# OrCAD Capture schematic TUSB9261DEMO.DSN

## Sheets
1 PAGE1: size C; title: TUSB9261 DEMO EVM; rev: A; company: Texas Instruments; note: TUSB9261 DEMO
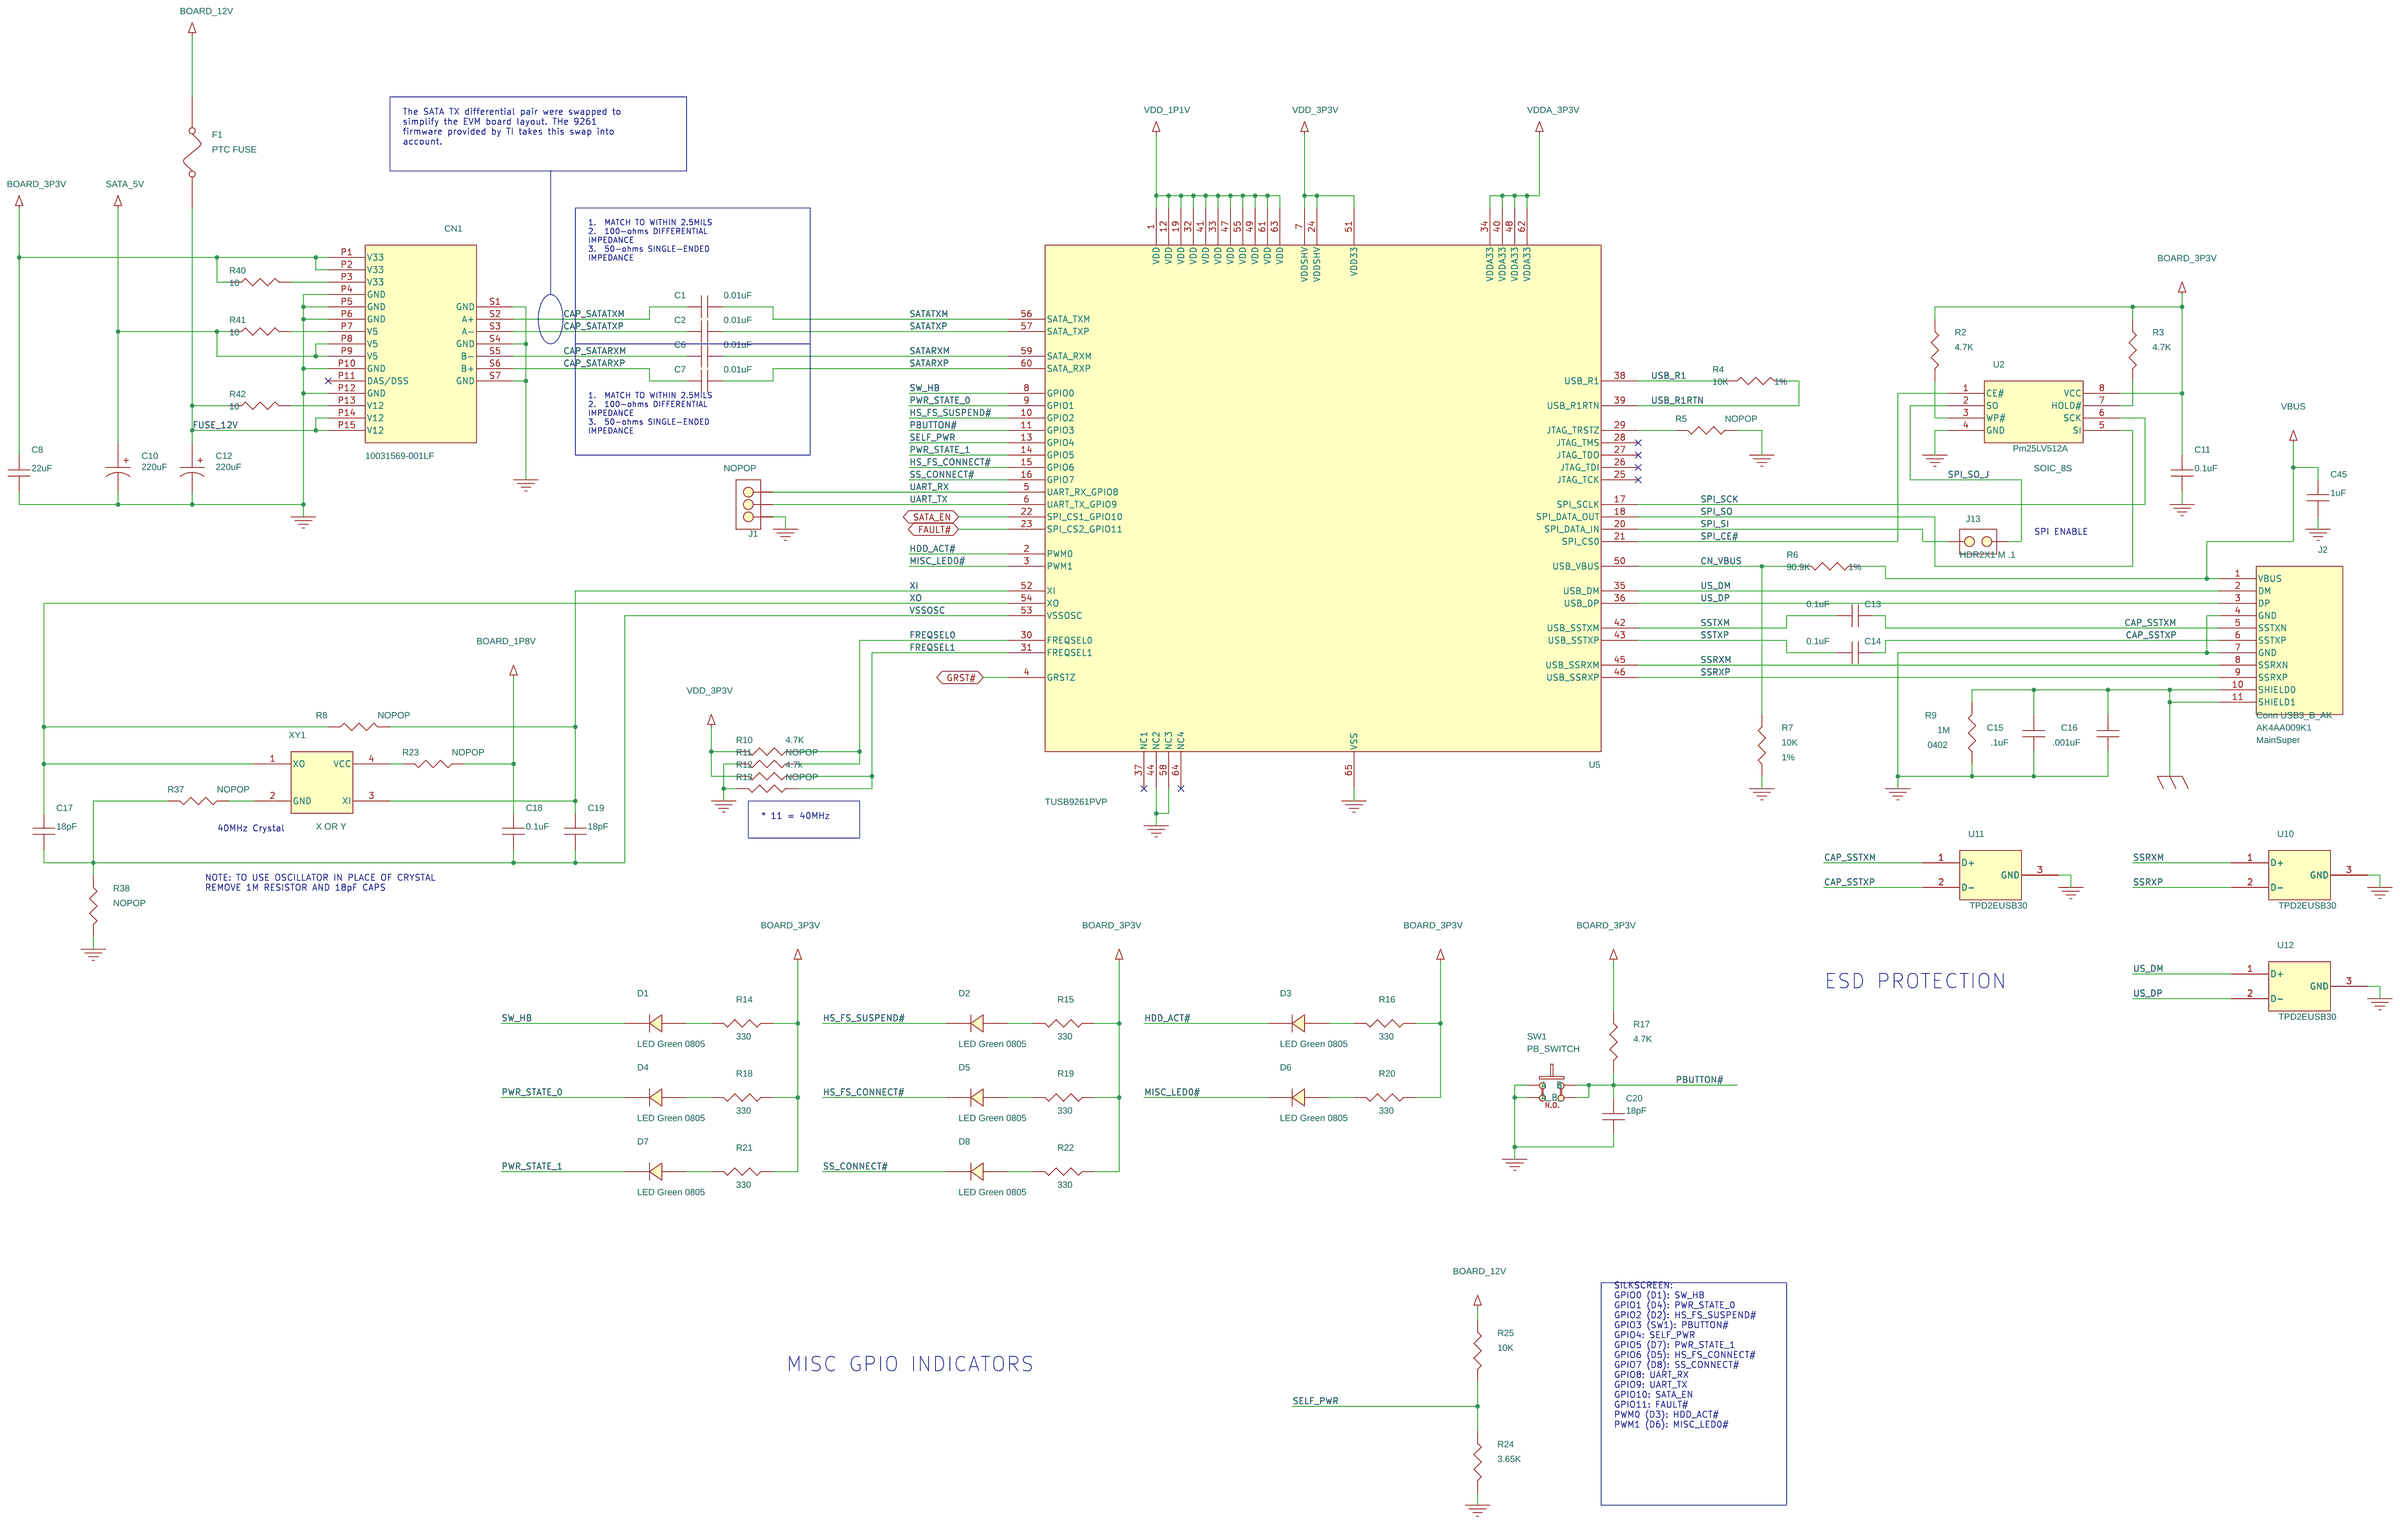
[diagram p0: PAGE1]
2 PAGE2: size C; note: POWER
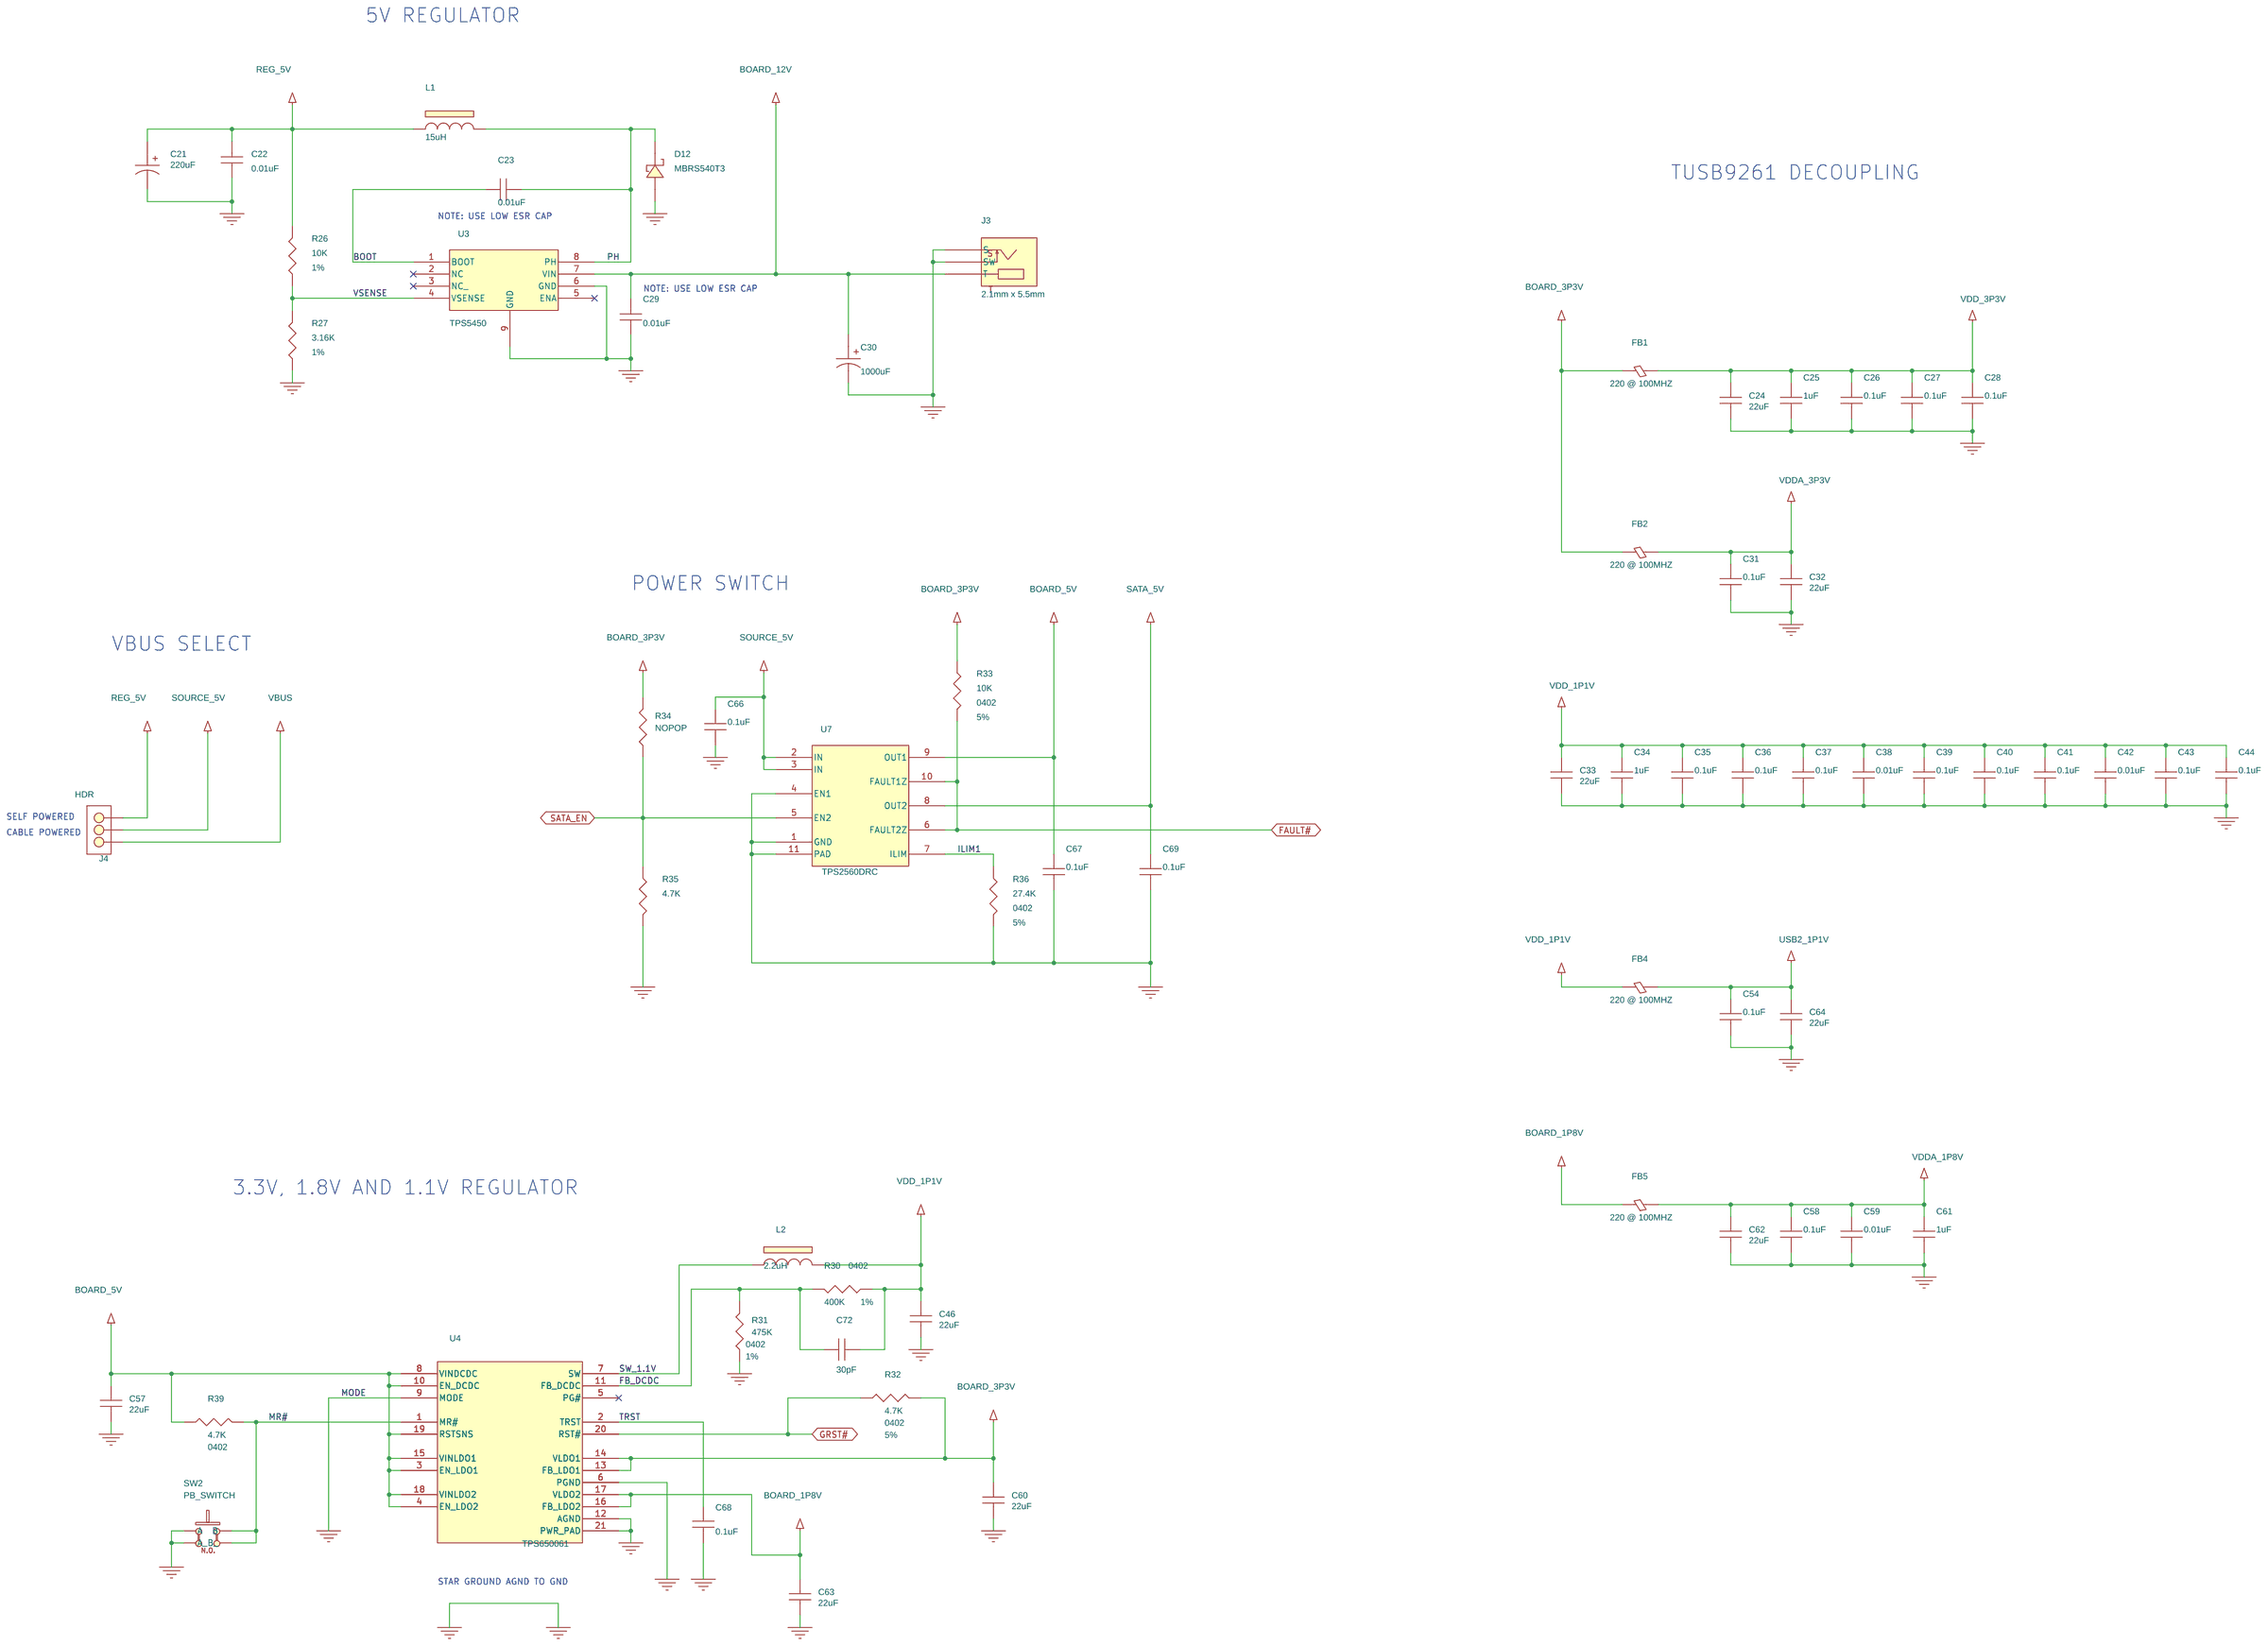
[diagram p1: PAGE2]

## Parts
sheet PAGE1
C1  0.01uF  [0402]
C2  0.01uF  [0402]
C6  0.01uF  [0402]
C7  0.01uF  [0402]
C8  22uF  [0805]
C10  220uF  [THCAP_2P5MM]
C11  0.1uF  [0402]
C12  220uF  [THCAP_2P5MM]
C13  0.1uF  [0201]
C14  0.1uF  [0201]
C15  .1uF  [0402]
C16  .001uF  [0402]
C17  18pF  [0402]
C18  0.1uF  [0402]
C19  18pF  [0402]
C20  18pF  [0402]
C45  1uF  [0402]
CN1  10031569-001LF  [CONN_10031569]
D1  LED Green 0805  [0805]
D2  LED Green 0805  [0805]
D3  LED Green 0805  [0805]
D4  LED Green 0805  [0805]
D5  LED Green 0805  [0805]
D6  LED Green 0805  [0805]
D7  LED Green 0805  [0805]
D8  LED Green 0805  [0805]
F1  PTC FUSE  [FUSE_2920L]
J1  NOPOP  [eprt-head-00001-0000]
J2  Conn USB3_B_AK  [USB3_TYPEB_AK4AA009]
J13  HDR2X1 M .1  [HDR_2X1]
R2  4.7K  [0402]
R3  4.7K  [0402]
R4  10K  [0402]
R5  NOPOP  [0402]
R6  90.9K  [0402]
R7  10K  [0402]
R8  NOPOP  [0402]
R9  1M  [0402]
R10  4.7K  [0402]
R11  NOPOP  [0402]
R12  4.7k  [0402]
R13  NOPOP  [0402]
R14  330  [0402]
R15  330  [0402]
R16  330  [0402]
R17  4.7K  [0402]
R18  330  [0402]
R19  330  [0402]
R20  330  [0402]
R21  330  [0402]
R22  330  [0402]
R23  NOPOP  [0402]
R24  3.65K  [0402]
R25  10K  [0402]
R37  NOPOP  [0402]
R38  NOPOP  [0402]
R40  10  [0805]
R41  10  [0805]
R42  10  [0805]
SW1  PB_SWITCH  [SW_MOM_2NO]
U2  Pm25LV512A  [SOIC_8S]
U5  TUSB9261PVP  [ironwood_64pin_c9508]
U10  TPD2EUSB30  [DRT_r_pdso_n3_sot23]
U11  TPD2EUSB30  [DRT_r_pdso_n3_sot23]
U12  TPD2EUSB30  [DRT_r_pdso_n3_sot23]
XY1  X OR Y  [ECX-53B]
sheet PAGE2
C21  220uF  [THCAP_2P5MM]
C22  0.01uF  [0402]
C23  0.01uF  [0402]
C24  22uF  [0805]
C25  1uF  [0402]
C26  0.1uF  [0402]
C27  0.1uF  [0402]
C28  0.1uF  [0402]
C29  0.01uF  [0402]
C30  1000uF  [THCAP_5MM]
C31  0.1uF  [0402]
C32  22uF  [0805]
C33  22uF  [0805]
C34  1uF  [0402]
C35  0.1uF  [0402]
C36  0.1uF  [0402]
C37  0.1uF  [0402]
C38  0.01uF  [0402]
C39  0.1uF  [0402]
C40  0.1uF  [0402]
C41  0.1uF  [0402]
C42  0.01uF  [0402]
C43  0.1uF  [0402]
C44  0.1uF  [0402]
C46  22uF  [0805]
C54  0.1uF  [0402]
C57  22uF  [0805]
C58  0.1uF  [0402]
C59  0.01uF  [0402]
C60  22uF  [0805]
C61  1uF  [0402]
C62  22uF  [0805]
C63  22uF  [0805]
C64  22uF  [0805]
C66  0.1uF  [0402]
C67  0.1uF  [0402]
C68  0.1uF  [0402]
C69  0.1uF  [0402]
C72  30pF  [0402]
D12  MBRS540T3  [DIODE_SMC]
FB1  220 @ 100MHZ  [0603]
FB2  220 @ 100MHZ  [0603]
FB4  220 @ 100MHZ  [0603]
FB5  220 @ 100MHZ  [0603]
J3  2.1mm x 5.5mm  [PJ-202AH]
J4  HDR  [eprt-head-00001-0000]
L1  15uH  [DR127]
L2  2.2uH  [IND_SM_VLCF_4X4X2MM]
R26  10K  [0402]
R27  3.16K  [0402]
R30  400K  [0402]
R31  475K  [0402]
R32  4.7K  [0402]
R33  10K  [0402]
R34  NOPOP  [0402]
R35  4.7K  [0402]
R36  27.4K  [0402]
R39  4.7K  [0402]
SW2  PB_SWITCH  [SW_MOM_2NO]
U3  TPS5450  [DDA_R-PDSO-G8]
U4  TPS650061  [RUK_s-pqfp-n20]
U7  TPS2560DRC  [DRC_S_PVSON_N10]

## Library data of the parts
C1 C2 C6-C8 C11 C13-C20 C22-C29 C31-C46 C54 C57-C64 C66-C69 C72 = CAP_NP
C10 C12 C21 = CAP_POL: Manuf: Panasonic; Manuf PN: ECA-1CM221
CN1 = 0876781001: Manuf: FCI
D1-D8 = DIODE: Manuf: Lumex; Manuf PN: SML-LX0805GC-TR; TI_Silktext: LEDG1
F1 = FUSE: Manuf: Littelfuse; Manuf PN: 2920L200/24DR
J1 J4 = HDR3X1_M_.1
J2 = USB3_TYPEB_CONNECTOR: Connector USB3 TYPE B; Manuf: MainSuper; Manuf PN: AK4AA009K1; Manufacturer: MainSuper; Manufacturer's Part#: AK4AA009K1; PART_NUMBER: USB3_UP0; Part#: eprt-conn-00064-0100; Status: OK; TI_Silktext: USB3_UP0
J13 = HDR2X1_M_.1
R2 R3 R5 R8-R25 R32-R42 = R: Tolerance: 5%
R4 R6 R7 R26 R27 R30 R31 = R: Tolerance: 1%
SW1 SW2 = PB_SWITCH_0: Manuf: OMRON; Manuf PN: B3SN-3012P; PART_NUMBER: BRD_RESETN; Part#: B3SN-3012P; TI_Silktext: BRD_RESETN
U2 = Pm25LV512A: Manuf: Chingistek; Manuf PN: Pm25LV512A-100SCE
U5 = TUSB9260PAP_0
U10-U12 = TPD2E009: Manuf PN: TPD2EUSB30DRT
XY1 = X_OR_Y: Manuf PN: ECS-250-20-30B-TR
C30 = CAP_POL: Manuf: Panasonic; Manuf PN: ECA-1CM102
D12 = DIODE_SCHOTTKY: Manuf: On Semiconductor; Manuf PN: MBRS540T3G
FB1 FB2 FB4 FB5 = FERRITE_BEAD: FBEAD 1000@100MHz; Device: BEAD1806; MFC: MuRata; Manuf: MuRata; Manuf PN: BLM18EG221SN1D; Part Number: BLM18EG221SN1D; Part#: BLM18EG221SN1D
J3 = BNC_2: POWER JACK; COST: .12; MANUF: CUI STACK; PART_NUMBER: 5V_SUPPLY; TI_Silktext: 5V_SUPPLY
L1 = INDUCTOR_FERRITE: Manuf: Coiltronics; Manuf PN: DR127-150-R
L2 = INDUCTOR_FERRITE: Manuf: TDK; Manuf PN: VLCF4020T-2R2N1R7
U3 = TPS5450_2: Manuf: Texas Instruments; Manuf PN: TPS5450DDAR
U4 = TPS650061_0
U7 = TPS2560DRC_1: Manuf: Texas Instruments

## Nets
AGND: C8.2 C10.2 C11.2 C12.2 C15.1 C16.1 C20.1 C21.2 C22.1 C24.2 C25.2 C26.2 C27.2 C28.2 C29.1 C30.2 C31.2 C32.2 C33.2 C34.2 C35.2 C36.2 C37.2 C38.2 C39.2 C40.2 C41.2 C42.2 C43.2 C44.2 C45.2 C46.2 C54.2 C57.2 C58.2 C59.2 C60.2 C61.2 C62.2 C63.2 C64.2 C66.2 C67.2 C68.2 C69.2 CN1.P4(GND) CN1.P5(GND) CN1.P6(GND) CN1.P10(GND) CN1.P12(GND) CN1.S1(GND) CN1.S4(GND) CN1.S7(GND) D12.1(ANODE) J1.1 J2.4(GND) J2.7(GND) J3.2(S) J3.3(SW) R5.1 R7.1 R9.2 R11.2 R13.2 R24.2 R27.1 R31.1 R35.2 R36.2 R38.2 SW1.1(A) SW1.2(A_) SW2.1(A) SW2.2(A_) U2.4(GND) U3.6(GND) U3.9(GND) U4.6(PGND) U4.9(MODE) U4.12(AGND) U4.21(PWR_PAD) U5.44(NC2) U5.58(NC3) U5.65(VSS) U7.1(GND) U7.4(EN1) U7.11(PAD) U10.3(GND) U11.3(GND) U12.3(GND)
GND_EARTH: C15.2 C16.2 J2.10(SHIELD0) J2.11(SHIELD1) R9.1
VBUS: C45.1 J2.1(VBUS) J4.1 R6.1
VDD_1P1V: C33.1 C34.1 C35.1 C36.1 C37.1 C38.1 C39.1 C40.1 C41.1 C42.1 C43.1 C44.1 C46.1 C72.2 FB4.1 L2.2 R30.1 U5.1(VDD) U5.12(VDD) U5.19(VDD) U5.32(VDD) U5.33(VDD) U5.41(VDD) U5.47(VDD) U5.49(VDD) U5.55(VDD) U5.61(VDD) U5.63(VDD)
VDD_3P3V: C24.1 C25.1 C26.1 C27.1 C28.1 FB1.2 R10.2 R12.2 U5.7(VDDSHV) U5.24(VDDSHV) U5.51(VDD33)
VDDA_1P8V: C58.1 C59.1 C61.1 C62.1 FB5.2
VDDA_3P3V: C31.1 C32.1 FB2.2 U5.34(VDDA33) U5.40(VDDA33) U5.48(VDDA33) U5.62(VDDA33)
VSSOSC: C17.2 C18.2 C19.2 R37.2 R38.1 U5.53(VSSOSC)
BOARD_1P8V: C18.1 C63.1 FB5.1 R23.1 U4.16(FB_LDO2) U4.17(VLDO2)
BOARD_3P3V: C8.1 C11.1 C60.1 CN1.P1(V33) CN1.P2(V33) FB1.1 FB2.1 R2.1 R3.1 R14.1 R15.1 R16.1 R17.1 R18.1 R19.1 R20.1 R21.1 R22.1 R32.2 R33.1 R34.2 R40.1 U2.8(VCC) U4.13(FB_LDO1) U4.14(VLDO1)
BOARD_5V: C57.1 C67.1 R39.1 U4.3(EN_LDO1) U4.4(EN_LDO2) U4.8(VINDCDC) U4.10(EN_DCDC) U4.15(VINLDO1) U4.18(VINLDO2) U4.19(RSTSNS) U7.9(OUT1)
BOARD_12V: C29.2 C30.1 F1.2 J3.1(T) R25.1 U3.7(VIN)
BOOT: C23.1 U3.1(BOOT)
CAP_SATARXM: C6.1 CN1.S5(B-)
CAP_SATARXP: C7.1 CN1.S6(B+)
CAP_SATATXM: C1.1 CN1.S2(A+)
CAP_SATATXP: C2.1 CN1.S3(A-)
CAP_SSTXM: C13.1 J2.5(SSTXN) U11.1(D+)
CAP_SSTXP: C14.1 J2.6(SSTXP) U11.2(D-)
CN_VBUS: R6.2 R7.2 U5.50(USB_VBUS)
FAULT#: R33.2 U5.23(SPI_CS2_GPIO11) U7.6(FAULT2Z) U7.10(FAULT1Z)
FB_DCDC: C72.1 R30.2 R31.2 U4.11(FB_DCDC)
FREQSEL0: R10.1 R11.1 U5.30(FREQSEL0)
FREQSEL1: R12.1 R13.1 U5.31(FREQSEL1)
FUSE_12V: C12.1 CN1.P14(V12) CN1.P15(V12) F1.1 R42.1
GRST#: R32.1 U4.20(RST#) U5.4(GRSTZ)
HDD_ACT#: D3.2(K) U5.2(PWM0)
HS_FS_CONNECT#: D5.2(K) U5.15(GPIO6)
HS_FS_SUSPEND#: D2.2(K) U5.10(GPIO2)
ILIM1: R36.1 U7.7(ILIM)
MISC_LED0#: D6.2(K) U5.3(PWM1)
MR#: R39.2 SW2.3(B_) SW2.4(B) U4.1(MR#)
PBUTTON#: C20.2 R17.2 SW1.3(B_) SW1.4(B) U5.11(GPIO3)
PH: C23.2 D12.2(CATHODE) L1.2 U3.8(PH)
PWR_STATE_0: D4.2(K) U5.9(GPIO1)
PWR_STATE_1: D7.2(K) U5.14(GPIO5)
REG_5V: C21.1 C22.2 J4.3 L1.1 R26.2
SATA_5V: C10.1 C69.1 CN1.P8(V5) CN1.P9(V5) R41.1 U7.8(OUT2)
SATA_EN: R34.1 R35.1 U5.22(SPI_CS1_GPIO10) U7.5(EN2)
SATARXM: C6.2 U5.59(SATA_RXM)
SATARXP: C7.2 U5.60(SATA_RXP)
SATATXM: C1.2 U5.56(SATA_TXM)
SATATXP: C2.2 U5.57(SATA_TXP)
SELF_PWR: R24.1 R25.2 U5.13(GPIO4)
SOURCE_5V: C66.1 J4.2 U7.2(IN) U7.3(IN)
SPI_CE#: U2.1(CE#) U5.21(SPI_CS0)
SPI_SCK: U2.6(SCK) U5.17(SPI_SCLK)
SPI_SI: J13.1 U5.20(SPI_DATA_IN)
SPI_SO: U2.5(SI) U5.18(SPI_DATA_OUT)
SPI_SO_J: J13.2 U2.2(SO)
SS_CONNECT#: D8.2(K) U5.16(GPIO7)
SSRXM: J2.8(SSRXN) U5.45(USB_SSRXM) U10.1(D+)
SSRXP: J2.9(SSRXP) U5.46(USB_SSRXP) U10.2(D-)
SSTXM: C13.2 U5.42(USB_SSTXM)
SSTXP: C14.2 U5.43(USB_SSTXP)
SW_1.1V: L2.1 U4.7(SW)
SW_HB: D1.2(K) U5.8(GPIO0)
TRST: C68.1 U4.2(TRST)
UART_RX: J1.3 U5.5(UART_RX_GPIO8)
UART_TX: J1.2 U5.6(UART_TX_GPIO9)
US_DM: J2.2(DM) U5.35(USB_DM) U12.1(D+)
US_DP: J2.3(DP) U5.36(USB_DP) U12.2(D-)
USB2_1P1V: C54.1 C64.1 FB4.2
USB_R1: R4.1 U5.38(USB_R1)
USB_R1RTN: R4.2 U5.39(USB_R1RTN)
VSENSE: R26.1 R27.2 U3.4(VSENSE)
XI: C19.1 R8.2 U5.52(XI) XY1.3(XI)
XO: C17.1 R8.1 U5.54(XO) XY1.1(XO)
N50426: R3.2 U2.7(HOLD#)
N52215: R2.2 U2.3(WP#)
N191797: R5.2 U5.29(JTAG_TRSTZ)
N372931: D1.1(A) R14.2
N373403: D4.1(A) R18.2
N373877: D7.1(A) R21.2
N388253: D2.1(A) R15.2
N388277: D5.1(A) R19.2
N388301: D8.1(A) R22.2
N389292: D3.1(A) R16.2
N389316: D6.1(A) R20.2
N815346: R23.2 XY1.4(VCC)
N990729: R37.1 XY1.2(GND)
N1011037: CN1.P3(V33) R40.2
N1019902: CN1.P7(V5) R41.2
N1022218: CN1.P13(V12) R42.2

Not connected (* = marked no-connect by the designer): CN1 P11(DAS/DSS)*; U3 2(NC)* 3(NC_)* 5(ENA)*; U4 5(PG#)*; U5 25(JTAG_TCK)* 26(JTAG_TDI)* 27(JTAG_TDO)* 28(JTAG_TMS)* 37(NC1)* 64(NC4)*

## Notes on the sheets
sheet 1
- The SATA TX differential pair were swapped to
  simplify the EVM board layout. THe 9261
  firmware provided by TI takes this swap into
  account.
- 1.  MATCH TO WITHIN 2.5MILS
  2.  100-ohms DIFFERENTIAL
  IMPEDANCE
  3.  50-ohms SINGLE-ENDED
  IMPEDANCE
- 1.  MATCH TO WITHIN 2.5MILS
  2.  100-ohms DIFFERENTIAL
  IMPEDANCE
  3.  50-ohms SINGLE-ENDED
  IMPEDANCE
- SPI ENABLE
- * 11 = 40MHz
- 40MHz Crystal
- NOTE: TO USE OSCILLATOR IN PLACE OF CRYSTAL
  REMOVE 1M RESISTOR AND 18pF CAPS
- ESD PROTECTION
- SILKSCREEN:
  GPIO0 (D1): SW_HB
  GPIO1 (D4): PWR_STATE_0
  GPIO2 (D2): HS_FS_SUSPEND#
  GPIO3 (SW1): PBUTTON#
  GPIO4: SELF_PWR
  GPIO5 (D7): PWR_STATE_1
  GPIO6 (D5): HS_FS_CONNECT#
  GPIO7 (D8): SS_CONNECT#
  GPIO8: UART_RX
  GPIO9: UART_TX
  GPIO10: SATA_EN
  GPIO11: FAULT#
  PWM0 (D3): HDD_ACT#
  PWM1 (D6): MISC_LED0#
- MISC GPIO INDICATORS
sheet 2
- 5V REGULATOR
- TUSB9261 DECOUPLING
- NOTE: USE LOW ESR CAP
- NOTE: USE LOW ESR CAP
- POWER SWITCH
- VBUS SELECT
- SELF POWERED
- CABLE POWERED
- 3.3V, 1.8V AND 1.1V REGULATOR
- STAR GROUND AGND TO GND
